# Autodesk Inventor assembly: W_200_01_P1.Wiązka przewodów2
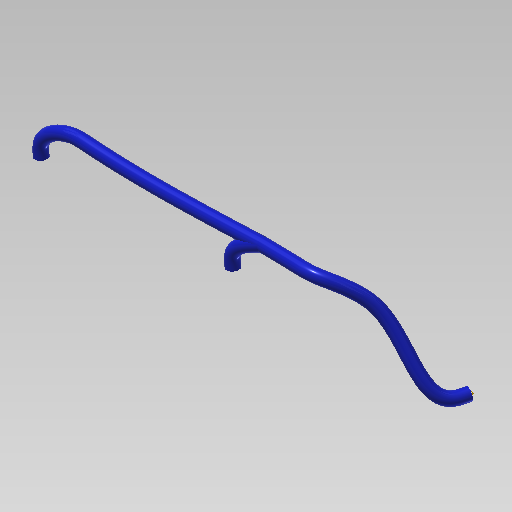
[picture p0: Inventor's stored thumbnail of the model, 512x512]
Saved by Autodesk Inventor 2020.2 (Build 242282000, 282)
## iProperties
Manager: www.cadconsulting.pl
Company: Fabian Stasiak CAD Consulting
ParentFileIdentifier: 5|1|0|0|30|1|0|0|80|0|65|0|84|0|72|0|83|0|59|0|67|0|58|0|92|0|90|0|98|0|105|0|243|0|114|0|32|0|7|1|119|0|105|0|99|0|122|0|101|0|68|1|32|0|65|0|73|0|32|0|50|0|48
Created: 2014-09
Part Number: W_200_01_P1.Wiązka przewodów2
Document SubType Name: Assembly
Designer: F.Stasiak
Catalog Web Link: www.expertbooks.pl
HarnessSettings: <HarnessSettings><Defaults><Segments><Diameter value="0.200 in" fromwires="True"/><Offset value="0.100 in"/><ColorStyle value="Niebieska - farba ścienna - lśnią
Author: F.Stasiak
Subject: Zbiór ćwiczeń. Autodesk Inventor 2020. Kurs Professional
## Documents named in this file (2)
- C:\2020_Kurs_Professional\R2 Wiązki\W_200_01_P1\AIP\przewody i wiązki przewodów\W_200_01_P1.Wiązka przewodów2.iam
- C:\2020_Kurs_Professional\R2 Wiązki\W_200_01_P1\AIP\przewody i wiązki przewodów\W_200_01_P1.Wiązka przewodów2.ipt
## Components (1 placed, 1 different names)
1. Wiązka przewodów2
